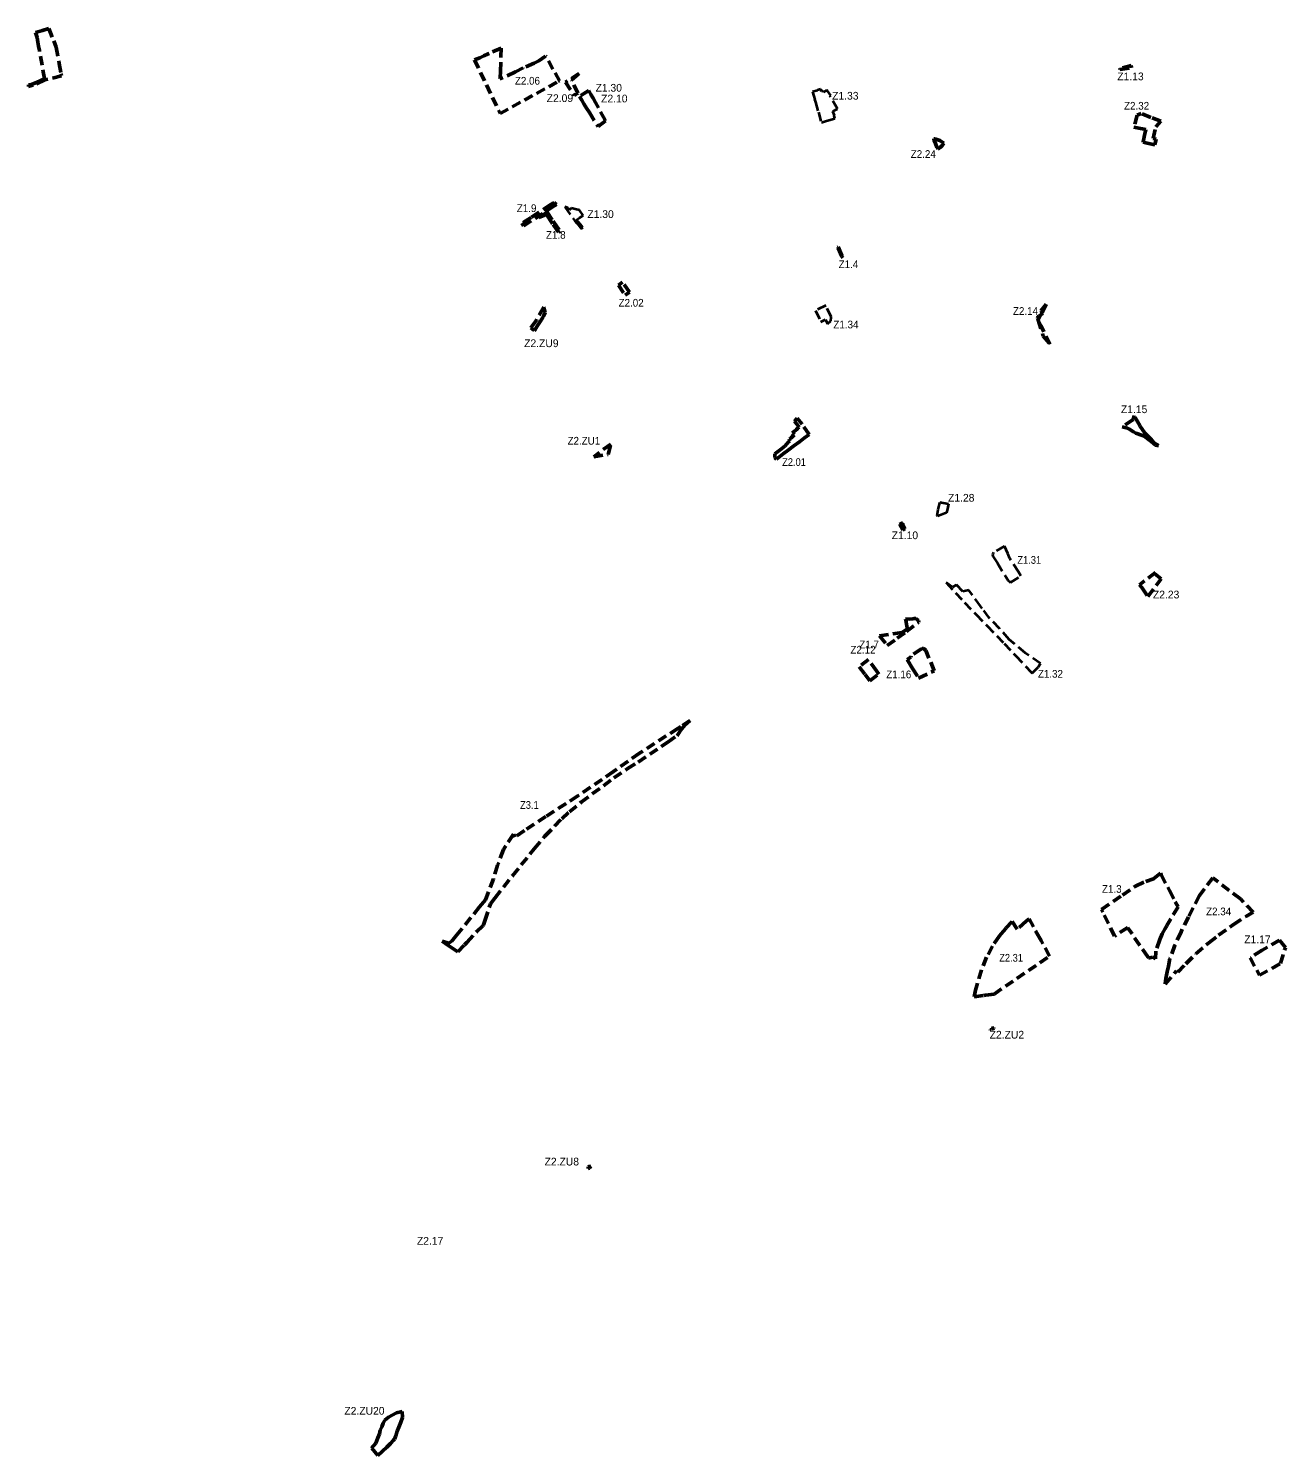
# Model space of a CAD drawing. Extents: x -650368 to -643203, y -1074215 to -1066658.
# Drawn here: x -649708 to -646290, y -1074215 to -1070336 of the extents above; entities that cross this region are included whole.
import ezdxf
from ezdxf.enums import TextEntityAlignment as Align

# ---------------------------------------------------------------- set-up
doc = ezdxf.new("R2010")
doc.units = 0
doc.header["$LTSCALE"] = 8.4
doc.linetypes.add('MEDIUM_DASHED', pattern=[4.5, 3, -1.5])
for name, color, linetype in [('55', 7, 'Continuous'), ('60', 7, 'Continuous'), ('61', 7, 'Continuous'), ('62', 7, 'Continuous')]:
    doc.layers.add(name, color=color, linetype=linetype)
for name, color, linetype, lineweight in [('56', 7, 'MEDIUM_DASHED', 53), ('57', 7, 'MEDIUM_DASHED', 40), ('58', 7, 'MEDIUM_DASHED', 53), ('59', 7, 'MEDIUM_DASHED', 53)]:
    doc.layers.add(name, color=color, linetype=linetype, lineweight=lineweight)

msp = doc.modelspace()

# ---------------------------------------------------------------- linework, layer by layer
at = {"layer": '56'}
for points in [[(-648391.796, -1072639.344), (-648333.178, -1072565.837), (-648303.791, -1072531.792), (-648258.165, -1072484.283), (-648237.406, -1072465.811), (-648205.298, -1072439.308), (-648116.32, -1072373.44), (-648079.76, -1072348.46), (-648050.276, -1072330.025), (-647969.894, -1072276.479), (-647944.45, -1072258.458), (-647941.77, -1072254.45), (-647934.9, -1072244.55), (-647923.16, -1072229.85), (-647908.5, -1072217.29), (-647933.95, -1072233.18), (-647942.21, -1072238.54), (-648046.69, -1072306.3), (-648117.12, -1072356), (-648214.73, -1072422.41), (-648300.98, -1072478.1), (-648359.61, -1072515.85), (-648385.28, -1072534.41), (-648389.69, -1072526.36), (-648416.41, -1072567.43), (-648432.45, -1072610.56), (-648443.77, -1072648.02), (-648465.598, -1072704.228)], [(-648452.274, -1072715.637), (-648439.912, -1072699.826), (-648391.796, -1072639.344)], [(-648465.598, -1072704.228), (-648481.468, -1072723.736), (-648543.255, -1072800.016), (-648557.588, -1072817.727), (-648565.726, -1072822.048), (-648583.407, -1072817.256), (-648564.86, -1072829.45), (-648554.22, -1072836.89), (-648541.102, -1072846.281)], [(-648541.102, -1072846.281), (-648522.66, -1072826.92), (-648516.44, -1072820.39), (-648489.69, -1072791.37), (-648473.13, -1072775.58), (-648470.89, -1072772.42), (-648467.286, -1072761.426), (-648452.274, -1072715.637)]]:
    msp.add_lwpolyline(points, dxfattribs=at)
at = {"layer": '57', "lineweight": 53}
for points in [[(-649689.02, -1070346.94), (-649670.28, -1070341.35), (-649653.03, -1070336.2), (-649639.561, -1070370), (-649633, -1070386.46), (-649624.97, -1070431.24), (-649620.17, -1070459.09), (-649619.72, -1070461.73), (-649618.85, -1070465.12), (-649663.84, -1070475.94), (-649695.44, -1070490.03), (-649708.08, -1070493.61), (-649708.37, -1070489.38), (-649702.69, -1070488.94), (-649686.94, -1070482.59), (-649664.82, -1070473.32), (-649678.92, -1070395.81), (-649680.99, -1070384.52), (-649683.08, -1070373.11), (-649685.31, -1070360.88)], [(-646739.83, -1070444.94), (-646739.74, -1070447.98), (-646708.18, -1070442.69), (-646708.99, -1070436.76)], [(-648366.98, -1070865.44), (-648362.519, -1070872.788), (-648303.624, -1070834.844), (-648283.19, -1070821.23), (-648272.45, -1070814.075), (-648278.832, -1070808.761), (-648282.44, -1070810.84), (-648287.74, -1070814.32), (-648341.58, -1070849.98)], [(-648320.02, -1070850.16), (-648297.39, -1070835.36), (-648281.37, -1070860.23), (-648279.39, -1070862.98), (-648262.4, -1070886.58), (-648267.24, -1070889.9), (-648283.46, -1070865.74), (-648284.02, -1070864.91), (-648298.78, -1070842.92), (-648305.33, -1070843.62)], [(-647507.79, -1070930.48), (-647506.58, -1070929.86), (-647493.71, -1070959.89), (-647495.91, -1070955.93), (-647496.37, -1070956.17)], [(-647330.34, -1071678.82), (-647339.211, -1071683.431), (-647330.73, -1071700.09), (-647324.21, -1071696.2), (-647331.65, -1071681.7)], [(-647393.87, -1071987.45), (-647372.56, -1072013.58), (-647345.75, -1071993.72), (-647320.41, -1071975.27), (-647287.04, -1071950.34), (-647287.83, -1071945.52), (-647294.62, -1071939.95), (-647299.8, -1071940.18), (-647303.12, -1071940.66), (-647311.9, -1071942.01), (-647322.73, -1071940.89), (-647322.26, -1071943.87), (-647321.38, -1071949.5), (-647320.37, -1071955.14), (-647319.44, -1071960.39), (-647318.12, -1071967.77), (-647332.2, -1071978.11)], [(-646789.83, -1072730.68), (-646732.95, -1072691.68), (-646697.89, -1072667.65), (-646669.6, -1072654.53), (-646648.27, -1072647.48), (-646629.86, -1072632.07), (-646627.32, -1072636.95), (-646605.23, -1072679.37), (-646589.37, -1072709.83), (-646581.92, -1072723.91), (-646612.11, -1072774.56), (-646612.76, -1072775.67), (-646612.4, -1072775.05), (-646616.6, -1072782.31), (-646616.97, -1072782.9), (-646624.81, -1072797.42), (-646631.08, -1072812.68), (-646642.404, -1072844.195), (-646643.445, -1072864.732), (-646651.14, -1072860.57), (-646662.12, -1072863.28), (-646664.42, -1072859.9), (-646716.21, -1072783.78), (-646718.72, -1072780.09), (-646754.96, -1072803.29), (-646786.56, -1072737.88)], [(-646360.22, -1072909.57), (-646303.02, -1072877.74), (-646289.63, -1072834.04), (-646305.56, -1072814.43), (-646353.25, -1072841.63), (-646385.86, -1072862.59)]]:
    msp.add_lwpolyline(points, close=True, dxfattribs=at)
at = {"layer": '57'}
for points in [[(-647537.02, -1070503.71), (-647546, -1070508.8), (-647547.21, -1070505.8), (-647551.72, -1070507.63), (-647554.53, -1070500.69), (-647562.6, -1070503.96), (-647562.41, -1070504.46), (-647575.92, -1070508.61), (-647572.58, -1070520.08), (-647569.96, -1070529.21), (-647570.25, -1070529.29), (-647569.06, -1070533.49), (-647568.31, -1070536.13), (-647560.15, -1070563.59), (-647551.93, -1070591.24), (-647538.02, -1070587.26), (-647515.53, -1070580.81), (-647517.04, -1070572.92), (-647515.92, -1070572.48), (-647521.04, -1070561.51), (-647511.26, -1070556.25), (-647507.74, -1070554.36), (-647527.28, -1070521.45), (-647528.84, -1070518.82), (-647526.64, -1070517.92), (-647535.34, -1070505.95)], [(-648207.151, -1070878.029), (-648205.18, -1070880.5), (-648200.86, -1070877.05), (-648202.798, -1070874.754), (-648212.94, -1070862.74), (-648217.85, -1070856.93), (-648218.11, -1070856.44), (-648209.37, -1070850.44), (-648200.17, -1070844.094), (-648209.66, -1070829.88), (-648221.58, -1070827.03), (-648231.22, -1070824.92), (-648237.46, -1070829.68), (-648241.96, -1070823.46), (-648249.5, -1070821.08), (-648222.158, -1070859.221), (-648217.1, -1070865.56)], [(-647229.63, -1071623.27), (-647206.3, -1071628.17), (-647209.092, -1071641.463), (-647211.91, -1071652.25), (-647217.42, -1071654.54), (-647234.94, -1071661.83), (-647237.25, -1071659.7), (-647233.89, -1071643.39), (-647230.86, -1071629.13)], [(-647184.81, -1071848.61), (-647185.62, -1071849.12), (-647194.96, -1071854.93), (-647205.62, -1071847.24), (-647212.66, -1071842.15), (-647163.08, -1071896.13), (-647131.146, -1071929.146), (-647101.07, -1071960.24), (-647055.16, -1072007.74), (-647023.04, -1072041.63), (-646981.35, -1072085.77), (-646978.602, -1072088.66), (-646962.041, -1072072.379), (-646956.04, -1072061.95), (-646996.8, -1072034.35), (-647040.89, -1071996.58), (-647067.53, -1071967.54), (-647095.51, -1071938.39), (-647114.479, -1071912.479), (-647118.79, -1071906.59), (-647151.07, -1071863.08), (-647167.15, -1071866.22)]]:
    msp.add_lwpolyline(points, close=True, dxfattribs=at)
for points in [[(-647539.818, -1071089.2), (-647568.01, -1071102.98), (-647553.01, -1071133.68)], [(-647525.1, -1071121.25), (-647524.95, -1071119.68), (-647539.817, -1071089.199)], [(-647553.01, -1071133.68), (-647540.48, -1071127.55), (-647534.851, -1071139.015), (-647526.04, -1071130.94), (-647525.1, -1071121.25)], [(-647053.43, -1071743.63), (-647083.97, -1071760.74), (-647084.95, -1071761.98), (-647085.71, -1071763.75), (-647086.19, -1071766.95), (-647085.25, -1071770.69), (-647074.99, -1071786.99)], [(-647009.514, -1071823.81), (-647016.12, -1071813.35), (-647039.14, -1071776.9), (-647044.83, -1071763.37), (-647053.43, -1071743.63)], [(-647074.99, -1071786.99), (-647073.19, -1071789.9), (-647044.12, -1071836.68)], [(-647044.12, -1071836.68), (-647040.2, -1071839.6), (-647037.23, -1071841.82), (-647009.514, -1071823.81)]]:
    msp.add_lwpolyline(points, dxfattribs=at)
at = {"layer": '57', "lineweight": 53}
for points in [[(-646669.77, -1071438.64), (-646671.02, -1071436.82), (-646686.04, -1071415.05), (-646701.52, -1071388.41), (-646703.84, -1071399.38), (-646704.58, -1071400.2), (-646734, -1071419.27), (-646719.23, -1071422.46), (-646715.7, -1071424.14), (-646703.15, -1071432.76), (-646696.59, -1071435.91), (-646678.5, -1071442.87)], [(-646678.5, -1071442.87), (-646673.89, -1071444.28), (-646670.05, -1071447.06), (-646662.55, -1071453.44), (-646655.29, -1071458.37), (-646643.4, -1071468.99), (-646638.52, -1071470.05), (-646634.56, -1071469.49), (-646645.57, -1071462.96), (-646654.25, -1071454.23), (-646669.77, -1071438.64)], [(-647271.92, -1072022.5), (-647274.99, -1072021.69), (-647277.91, -1072021.81), (-647280.99, -1072022.86), (-647308.09, -1072041.53), (-647308.4, -1072044.8), (-647318.52, -1072051.32)], [(-647287.34, -1072101.88), (-647244.88, -1072082.33), (-647267.71, -1072027.09)], [(-647267.71, -1072027.09), (-647269.43, -1072024.67), (-647271.92, -1072022.5)], [(-647318.52, -1072051.32), (-647315.92, -1072055.47), (-647303.63, -1072075.43), (-647287.34, -1072101.88)]]:
    msp.add_lwpolyline(points, dxfattribs=at)
at = {"layer": '58'}
for points in [[(-648495.666, -1070421.476), (-648425.835, -1070567.021), (-648267.801, -1070480.55), (-648263.859, -1070478.393), (-648282.01, -1070446.35), (-648302.01, -1070411.05), (-648320.24, -1070423.64), (-648332.97, -1070430.18), (-648362.79, -1070443.63), (-648363.1, -1070443.1), (-648383.61, -1070453.86), (-648426.05, -1070473.34), (-648425.71, -1070468.87), (-648424.47, -1070452.7), (-648423.56, -1070413.35), (-648423.005, -1070389.357), (-648455.85, -1070404.19), (-648457.94, -1070405.13), (-648469.77, -1070410.47), (-648481.18, -1070415.62)], [(-648184.54, -1070505.07), (-648210.19, -1070521.07), (-648203.83, -1070531.25), (-648197.59, -1070541.27), (-648190.71, -1070552.3), (-648182.98, -1070564.68), (-648159.23, -1070602.75), (-648138.93, -1070587.1), (-648140.05, -1070585.09), (-648166.63, -1070537.28), (-648172.96, -1070525.9), (-648178.7, -1070515.58), (-648184.54, -1070505.07)], [(-646701.87, -1070603.92), (-646693.18, -1070605.83), (-646669.59, -1070611.01), (-646672.13, -1070622.41), (-646672.99, -1070626.23), (-646673.91, -1070630.38), (-646675.27, -1070636.43), (-646676.81, -1070643.36), (-646677.13, -1070644.78), (-646665.42, -1070647.54), (-646645.03, -1070652.34), (-646641.09, -1070636.89), (-646649.71, -1070634.85), (-646642.32, -1070603.3), (-646628.69, -1070588.27), (-646655.95, -1070577.64), (-646682.29, -1070567.36), (-646692.98, -1070571.45)], [(-647245.6, -1070636.4), (-647246.49, -1070638.53), (-647241.89, -1070648.94), (-647237.61, -1070658.33), (-647235.02, -1070664.1), (-647227.76, -1070658.33), (-647224.57, -1070655.48), (-647224.37, -1070655.59), (-647218.44, -1070647.43), (-647229.34, -1070640.91), (-647243.28, -1070636.43)], [(-648341.943, -1071150.071), (-648333.002, -1071157.07), (-648330.78, -1071154.36), (-648324.82, -1071145.25), (-648319.77, -1071137.52), (-648309.41, -1071121.655), (-648307.33, -1071118.47), (-648303.08, -1071108.16), (-648306.31, -1071097.36), (-648305.83, -1071096.48), (-648306.39, -1071093.99), (-648326.92, -1071128.68), (-648328.9, -1071132.02), (-648332.09, -1071136.43)], [(-646940.67, -1071085.15), (-646955.39, -1071103.23), (-646951.831, -1071107.765), (-646955.138, -1071114.466), (-646960.72, -1071117.25), (-646964.973, -1071123.095), (-646964.291, -1071125.474), (-646962.591, -1071128.96), (-646948.286, -1071172.534), (-646929.64, -1071194.58), (-646955.2, -1071143.67), (-646962.471, -1071129.325), (-646955.138, -1071114.466), (-646949.12, -1071111.22), (-646951.831, -1071107.765)], [(-647597.54, -1071448.75), (-647585.273, -1071440.044), (-647603.9, -1071412.1), (-647617.49, -1071394.901), (-647625.428, -1071403.267), (-647612.269, -1071419.742), (-647616.75, -1071423.83), (-647619.75, -1071426.57), (-647626.65, -1071432.87), (-647630.04, -1071435.97), (-647626.34, -1071440.73), (-647628.21, -1071443.09), (-647631.16, -1071445.79), (-647634.12, -1071448.49), (-647638.4, -1071452.55), (-647639.11, -1071452.78), (-647639.64, -1071453.33), (-647636.48, -1071457.52), (-647640.04, -1071458.97), (-647651.2, -1071471.24), (-647664.16, -1071481.45), (-647678.56, -1071492.25), (-647678.3, -1071502.55), (-647676.51, -1071504.34), (-647674.28, -1071506.59), (-647655.59, -1071492.52), (-647642.45, -1071482.62), (-647626.7, -1071470.46), (-647611.82, -1071459.38)], [(-648170.93, -1071500), (-648132.14, -1071493.74), (-648125, -1071465.96)], [(-646664.304, -1071879.909), (-646627.89, -1071832.14), (-646645.26, -1071818.72), (-646643.11, -1071814.6), (-646686.45, -1071848.26), (-646680.17, -1071856.05)], [(-647449.29, -1072071.08), (-647433.06, -1072092.41), (-647419.85, -1072109.65), (-647395.88, -1072091.34), (-647401.58, -1072082.32), (-647423.49, -1072051.76)], [(-646987.154, -1072756.377), (-646995.02, -1072762.45), (-647019.06, -1072784.57), (-647032.7, -1072763.68), (-647050.51, -1072782.79), (-647063.04, -1072796.74), (-647067.22, -1072802.77), (-647086.65, -1072830.76), (-647102.38, -1072860.7), (-647116.33, -1072895.3), (-647132.47, -1072950.4), (-647136.39, -1072968.63), (-647110.32, -1072964.56), (-647107.01, -1072964.04), (-647105.4, -1072963.84), (-647082.36, -1072960.95), (-646931.1, -1072857.55), (-646954.51, -1072815.63), (-646956.845, -1072810.746)], [(-647092.58, -1073058.59), (-647092.67, -1073058), (-647090.83, -1073057.72)], [(-647087.96, -1073056.29), (-647088.34, -1073053.92), (-647081.66, -1073052.93), (-647081.63, -1073053.13)], [(-648179.07, -1073428.81), (-648183.46, -1073429.52), (-648186.46, -1073430.01), (-648185.82, -1073435.12), (-648182.81, -1073434.38)], [(-648695.83, -1074124.88), (-648700.77, -1074138.18), (-648705.61, -1074149.4), (-648709.34, -1074161.26), (-648712.77, -1074170.51), (-648715.37, -1074173.28), (-648723.64, -1074182.09), (-648730.34, -1074189.22), (-648733.69, -1074192.38), (-648745.22, -1074203.28), (-648758.41, -1074215.05), (-648775.1, -1074194.97), (-648763.85, -1074181.6), (-648758.05, -1074167.41), (-648753.74, -1074156.28), (-648751.97, -1074146.03), (-648747.25, -1074137.56), (-648743.55, -1074127.69), (-648739.31, -1074119.01), (-648729.24, -1074110.84), (-648707.44, -1074098.79), (-648691.9, -1074095.66), (-648690.92, -1074111.64)]]:
    msp.add_lwpolyline(points, close=True, dxfattribs=at)
at = {"layer": '59'}
for points in [[(-648247.67, -1070481.57), (-648223.98, -1070518.025), (-648221.359, -1070516.349), (-648215.48, -1070512.59), (-648214.34, -1070511.86), (-648231.53, -1070476.99), (-648210.48, -1070458.42)], [(-648104.12, -1071033.78), (-648085.73, -1071060.92), (-648074.121, -1071052.749), (-648092.72, -1071025.89)], [(-646486.95, -1072644.87), (-646523.5, -1072692.86), (-646553.12, -1072751.12), (-646573.72, -1072791.74), (-646590.21, -1072827.45), (-646603.99, -1072863.84), (-646607.94, -1072885.41), (-646611.51, -1072900.28), (-646614.73, -1072918.29), (-646616.49, -1072934), (-646586.22, -1072897.88), (-646582.8, -1072901.17), (-646560.75, -1072878.59), (-646533.57, -1072851.83), (-646498.43, -1072821.57), (-646471.68, -1072801.15), (-646431.37, -1072771.48), (-646395.56, -1072748.73), (-646377.69, -1072738.13), (-646412.35, -1072701.92)]]:
    msp.add_lwpolyline(points, close=True, dxfattribs=at)

# ---------------------------------------------------------------- texts
at = {"layer": '55', "width": 0.9}
msp.add_text('Z3.1', height=21, dxfattribs=at).set_placement((-648346.051, -1072457.33), align=Align.CENTER)
at = {"layer": '60'}
for s, p in [('Z1.13', (-646711.241, -1070476.795)), ('Z1.30', (-648130.25, -1070507.749)), ('Z1.33', (-647486.769, -1070529.43)), ('Z1.30', (-648152.527, -1070851.191)), ('Z1.15', (-646701.349, -1071381.596)), ('Z1.28', (-647171.469, -1071622.255)), ('Z1.10', (-647324.762, -1071724.226)), ('Z1.17', (-646365.85, -1072822.584))]:
    msp.add_text(s, height=21, dxfattribs=at).set_placement(p, align=Align.CENTER)
for s, width, p in [('Z1.9', 0.95, (-648353.632, -1070835.005)), ('Z1.8', 0.95, (-648274.243, -1070907.64)), ('Z1.4', 0.95, (-647478.395, -1070987.579)), ('Z1.34', 0.95, (-647485.061, -1071151.263)), ('Z1.31', 0.9, (-646986.497, -1071791.238)), ('Z1.7', 0.95, (-647422.127, -1072021.075)), ('Z1.16', 0.95, (-647341.512, -1072102.293)), ('Z1.32', 0.95, (-646928.965, -1072100.798)), ('Z1.3', 0.95, (-646762.051, -1072685.488))]:
    msp.add_text(s, height=21, dxfattribs=dict(at, width=width)).set_placement(p, align=Align.CENTER)
at = {"layer": '61'}
for s, width, p in [('Z2.06', 0.95, (-648351.384, -1070488.722)), ('Z2.32', 0.95, (-646694.585, -1070556.682)), ('Z2.24', 0.95, (-647274.804, -1070687.883)), ('Z2.14', 0.95, (-646996.763, -1071114.597)), ('Z2.ZU1', 0.95, (-648197.892, -1071467.275)), ('Z2.01', 0.9, (-647626.341, -1071525.223)), ('Z2.12', 0.95, (-647438.697, -1072035.236)), ('Z2.31', 0.9, (-647035.914, -1072872.757))]:
    msp.add_text(s, height=21, dxfattribs=dict(at, width=width)).set_placement(p, align=Align.CENTER)
for s, p in [('Z2.10', (-648115.069, -1070536.986)), ('Z2.ZU9', (-648313.517, -1071202.172)), ('Z2.23', (-646614.24, -1071885.289)), ('Z2.ZU2', (-647047.431, -1073081.819)), ('Z2.ZU8', (-648257.993, -1073426.743)), ('Z2.ZU20', (-648794.75, -1074104.169))]:
    msp.add_text(s, height=21, dxfattribs=at).set_placement(p, align=Align.CENTER)
at = {"layer": '62'}
for s, p in [('Z2.09', (-648263.112, -1070535.96)), ('Z2.17', (-648616.086, -1073642.104))]:
    msp.add_text(s, height=21, dxfattribs=at).set_placement(p, align=Align.CENTER)
at = {"layer": '62', "width": 0.95}
for s, p in [('Z2.02', (-648069.383, -1071092.212)), ('Z2.34', (-646471.455, -1072746.692))]:
    msp.add_text(s, height=21, dxfattribs=at).set_placement(p, align=Align.CENTER)

doc.saveas('drawing.dxf')
